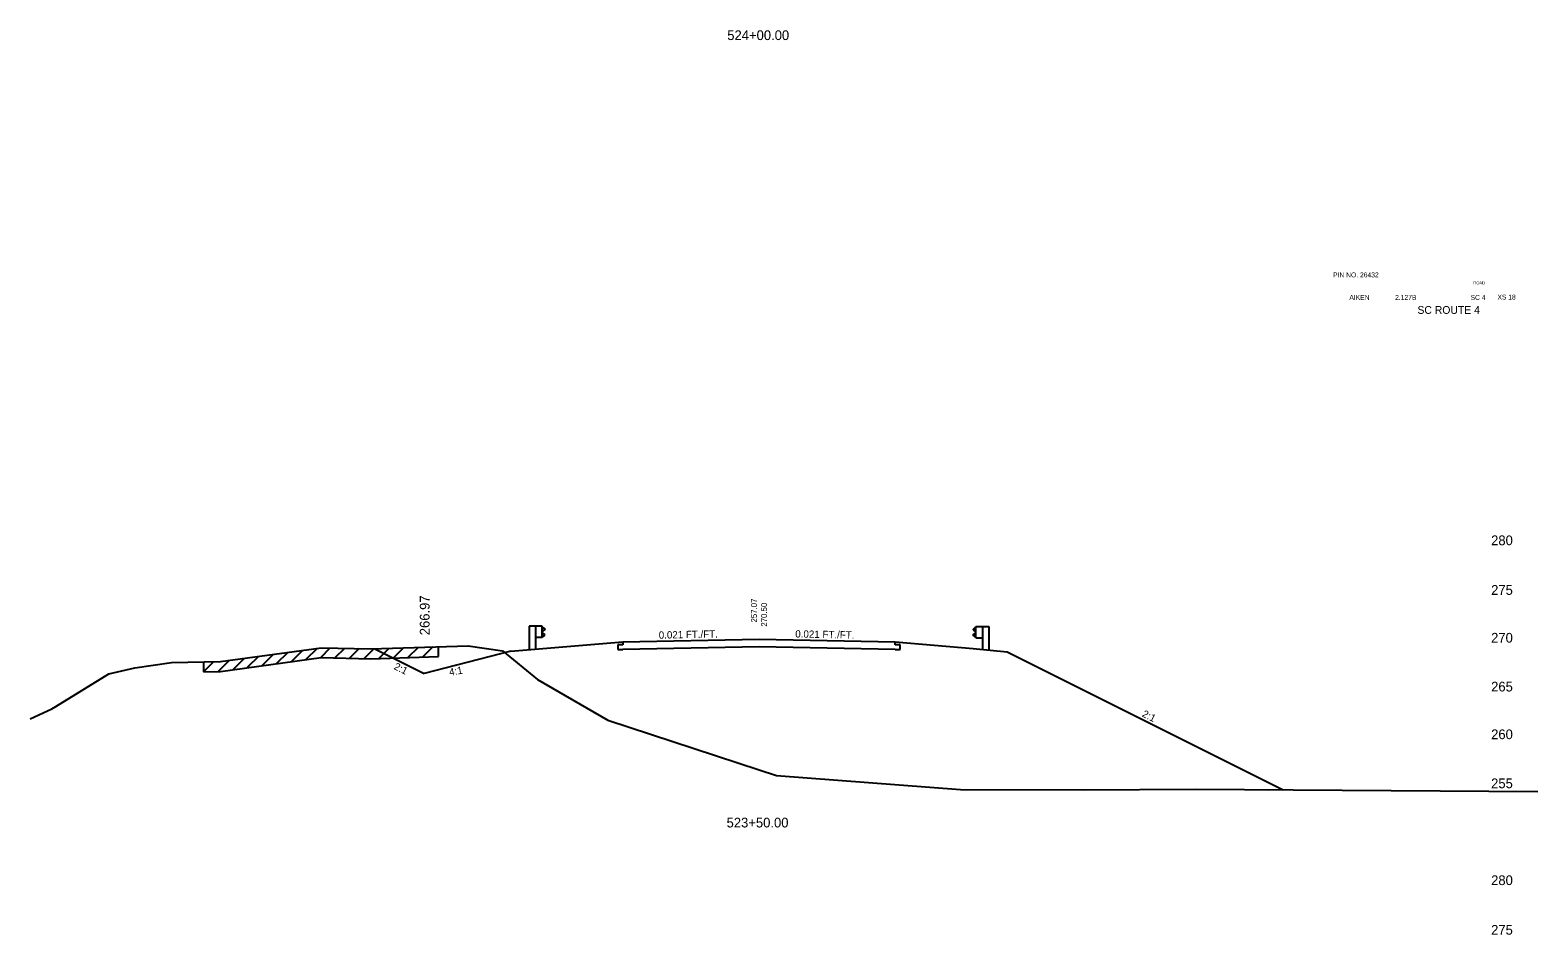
# Model space of a CAD drawing. Extents: x 883 to 1160, y 1002 to 4323.
# Drawn here: x 1005.1 to 1160, y 2990.1 to 3083.1 of the extents above; entities that cross this region are included whole.
import ezdxf

# ---------------------------------------------------------------- set-up
doc = ezdxf.new("R2010")
doc.units = 0
for name, color, linetype in [('Level 1', 7, 'Continuous'), ('Level 10', 7, 'Continuous'), ('Level 11', 7, 'Continuous'), ('Level 12', 7, 'Continuous'), ('Level 24', 7, 'Continuous'), ('Level 3', 7, 'Continuous'), ('Level 32', 7, 'Continuous'), ('Level 33', 7, 'Continuous'), ('Level 59', 7, 'Continuous'), ('Level 6', 7, 'Continuous'), ('Level 60', 7, 'Continuous'), ('Level 61', 7, 'Continuous'), ('Level 7', 7, 'Continuous')]:
    doc.layers.add(name, color=color, linetype=linetype)

msp = doc.modelspace()

# ---------------------------------------------------------------- linework, layer by layer
at = {"layer": 'Level 11'}
for p, q in [((1066, 3019.91), (1065.5, 3019.9)), ((1066, 3020.21), (1066, 3019.91)), ((1094, 3019.91), (1094, 3020.21)), ((1094.5, 3019.9), (1094, 3019.91)), ((1065.5, 3019.9), (1065.5, 3019.42)), ((1065.5, 3019.42), (1066, 3019.43)), ((1094, 3019.43), (1094.5, 3019.42)), ((1094.5, 3019.42), (1094.5, 3019.9))]:
    msp.add_line(p, q, dxfattribs=at)
at = {"layer": 'Level 12'}
for p, q in [((1080, 3019.72), (1066, 3019.43)), ((1094, 3019.43), (1080, 3019.72))]:
    msp.add_line(p, q, dxfattribs=at)
at = {"layer": 'Level 24'}
for p, q in [((1057.05, 3021.82), (1056.39, 3021.82)), ((1056.39, 3021.82), (1056.39, 3019.41)), ((1057.72, 3021.82), (1057.05, 3021.82)), ((1057.05, 3021.82), (1057.05, 3019.46)), ((1057.72, 3020.65), (1057.72, 3021.82)), ((1057.72, 3021.74), (1057.99, 3021.54)), ((1057.99, 3021.49), (1057.72, 3021.29)), ((1057.99, 3021.54), (1057.99, 3021.49)), ((1102.27, 3021.72), (1102, 3021.52)), ((1102, 3021.52), (1102, 3021.47)), ((1102, 3021.47), (1102.27, 3021.27)), ((1102.27, 3020.63), (1102.27, 3021.79)), ((1102.27, 3021.79), (1102.94, 3021.79)), ((1102.94, 3021.79), (1102.94, 3019.45)), ((1102.94, 3021.79), (1103.6, 3021.79)), ((1103.6, 3021.79), (1103.6, 3019.38)), ((1057.72, 3020.65), (1057.05, 3020.65)), ((1057.99, 3020.97), (1057.72, 3021.17)), ((1057.72, 3020.72), (1057.99, 3020.92)), ((1057.99, 3020.92), (1057.99, 3020.97)), ((1102, 3020.95), (1102.27, 3021.15)), ((1102, 3020.9), (1102, 3020.95)), ((1102.27, 3020.7), (1102, 3020.9)), ((1102.27, 3020.63), (1102.94, 3020.63))]:
    msp.add_line(p, q, dxfattribs=at)
at = {"layer": 'Level 59'}
for p, q in [((1066, 3020.21), (1080, 3020.5)), ((1080, 3020.5), (1094, 3020.21))]:
    msp.add_line(p, q, dxfattribs=at)
at = {"layer": 'Level 6'}
for p, q in [((1054.5, 3019.25), (1066, 3020.21)), ((1094, 3020.21), (1102, 3019.54)), ((1102, 3019.54), (1105.5, 3019.19))]:
    msp.add_line(p, q, dxfattribs=at)
at = {"layer": 'Level 60'}
for p, q in [((1024.67, 3018.19), (1035.03, 3019.6)), ((1035.03, 3019.6), (1040.13, 3019.49)), ((1040.13, 3019.49), (1050.13, 3019.82)), ((1050.13, 3019.82), (1053.66, 3019.31)), ((1053.66, 3019.31), (1057.23, 3016.35)), ((1007.77, 3013.59), (1013.22, 3016.95)), ((1013.22, 3016.95), (1015.89, 3017.56)), ((1015.89, 3017.56), (1019.65, 3018.09)), ((1019.65, 3018.09), (1024.67, 3018.19)), ((1057.23, 3016.35), (1064.47, 3012.18)), ((1005.13, 3012.3), (1007.35, 3013.34)), ((1007.35, 3013.34), (1007.77, 3013.59)), ((1064.47, 3012.18), (1080, 3007.07)), ((1080, 3007.07), (1081.78, 3006.48)), ((1081.78, 3006.48), (1100.68, 3005.05)), ((1100.68, 3005.05), (1113.37, 3005)), ((1113.37, 3005), (1124.84, 3005.09)), ((1124.84, 3005.09), (1160, 3004.83))]:
    msp.add_line(p, q, dxfattribs=at)
at = {"layer": 'Level 61'}
for p, q in [((1024.67, 3017.19), (1035.03, 3018.6)), ((1027.1, 3018.52), (1025.94, 3017.36)), ((1028.6, 3018.72), (1027.44, 3017.57)), ((1030.1, 3018.93), (1028.94, 3017.77)), ((1031.6, 3019.13), (1030.44, 3017.98)), ((1033.1, 3019.34), (1031.94, 3018.18)), ((1034.6, 3019.55), (1033.44, 3018.39)), ((1035.93, 3019.58), (1034.94, 3018.59)), ((1035.03, 3018.6), (1040.13, 3018.49)), ((1037.42, 3019.55), (1036.44, 3018.57)), ((1038.92, 3019.52), (1037.94, 3018.54)), ((1040.44, 3019.5), (1039.44, 3018.51)), ((1040.13, 3018.49), (1047.07, 3018.72)), ((1041.98, 3019.55), (1040.94, 3018.52)), ((1043.48, 3019.6), (1042.44, 3018.57)), ((1044.98, 3019.65), (1043.94, 3018.62)), ((1046.48, 3019.7), (1045.44, 3018.66)), ((1047.07, 3018.72), (1047.07, 3019.72)), ((1023.96, 3018.17), (1022.94, 3017.15)), ((1022.94, 3018.15), (1022.94, 3017.15)), ((1022.94, 3017.15), (1024.67, 3017.19)), ((1025.57, 3018.31), (1024.44, 3017.18))]:
    msp.add_line(p, q, dxfattribs=at)
at = {"layer": 'Level 7'}
for p, q in [((1040.55, 3019.51), (1045.62, 3016.97)), ((1054.5, 3019.25), (1045.62, 3016.97)), ((1105.5, 3019.19), (1133.84, 3005.02))]:
    msp.add_line(p, q, dxfattribs=at)

# ---------------------------------------------------------------- texts
at = {"layer": 'Level 1'}
for s, height, p in [('524+00.00', 1, (1076.74, 3082.05)), ('PIN NO. 26432', 0.5, (1138.97, 3057.67)), ('AIKEN', 0.5, (1140.64, 3055.36)), (' 2.127B', 0.5, (1145.15, 3055.36)), ('SC 4', 0.5, (1153.09, 3055.36)), ('XS 18', 0.5, (1155.85, 3055.39)), ('SC ROUTE 4', 0.8, (1147.63, 3053.92)), ('523+50.00', 1, (1076.67, 3001.15))]:
    msp.add_text(s, height=height, dxfattribs=at).set_placement(p)
at = {"layer": 'Level 10'}
msp.add_text('257.07', height=0.6, rotation=90, dxfattribs=at).set_placement((1079.79, 3022.21))
at = {"layer": 'Level 3'}
for s, height, p in [('ROAD', 0.3, (1153.38, 3056.95)), (' 280', 1, (1154.83, 3030.15)), (' 275', 1, (1154.83, 3025.05)), (' 270', 1, (1154.83, 3020.14)), (' 265', 1, (1154.83, 3015.12)), (' 260', 1, (1154.83, 3010.22)), (' 255', 1, (1154.83, 3005.18)), (' 280', 1, (1154.83, 2995.23)), (' 275', 1, (1154.83, 2990.13))]:
    msp.add_text(s, height=height, dxfattribs=at).set_placement(p)
at = {"layer": 'Level 32'}
for s, rotation, p in [('0.021 FT./FT.', 1.1916, (1069.71, 3020.54)), ('0.021 FT./FT.', 358.8084, (1083.72, 3020.67)), ('2:1', 333.435, (1042.43, 3017.45)), ('4:1', 9.4623, (1048.23, 3016.73)), ('2:1', 333.435, (1119.28, 3012.58))]:
    msp.add_text(s, height=0.75, rotation=rotation, dxfattribs=at).set_placement(p)
at = {"layer": 'Level 33'}
msp.add_text('266.97', height=1, rotation=90, dxfattribs=at).set_placement((1046.16, 3020.9))
at = {"layer": 'Level 59'}
msp.add_text(' 270.50', height=0.6, rotation=90, dxfattribs=at).set_placement((1080.82, 3021.56))

doc.saveas('drawing.dxf')
